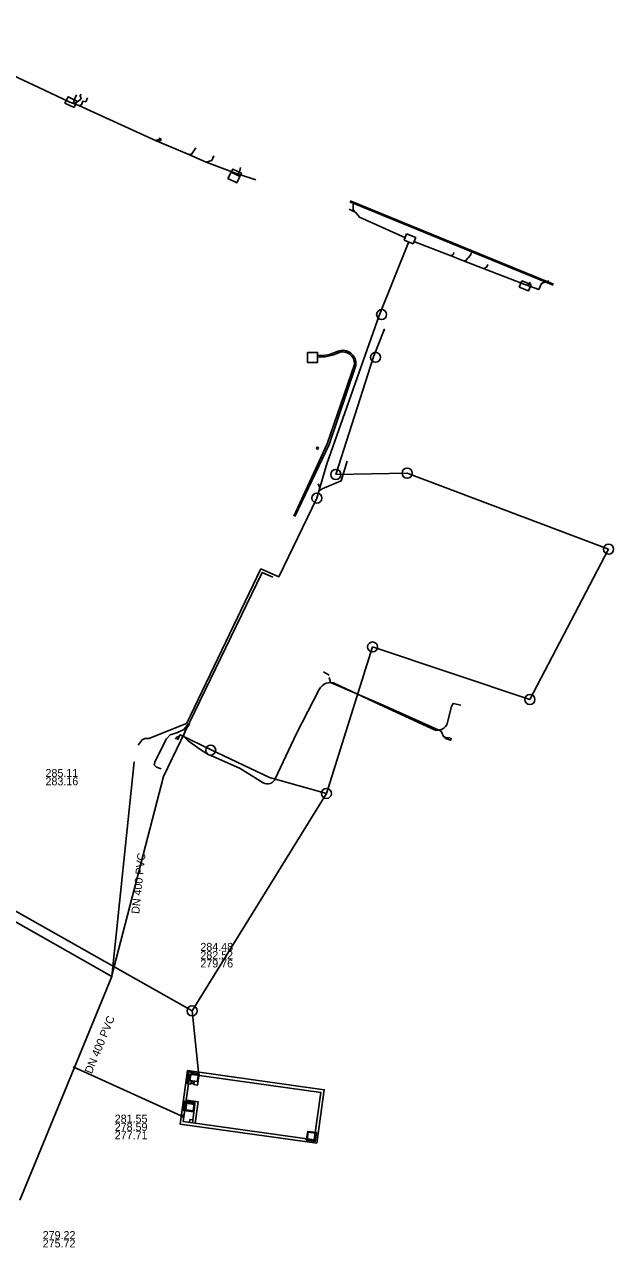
# Model space of a CAD drawing. Extents: x -600391 to -599491, y -1160176 to -1159402.
# Drawn here: x -599654.5 to -599595.6, y -1160008 to -1159885.7 of the extents above; entities that cross this region are included whole.
import ezdxf

# ---------------------------------------------------------------- set-up
doc = ezdxf.new("R2010")
doc.units = 0
for name, color, linetype in [('Vrstva 1', 7, 'Continuous'), ('Vrstva 12', 7, 'Continuous'), ('Vrstva 13', 7, 'Continuous'), ('Vrstva 15', 7, 'Continuous'), ('Vrstva 3', 7, 'Continuous'), ('Vrstva 5', 7, 'Continuous'), ('Vrstva 7', 7, 'Continuous'), ('Vrstva 9', 7, 'Continuous')]:
    doc.layers.add(name, color=color, linetype=linetype)

msp = doc.modelspace()

# ---------------------------------------------------------------- linework, layer by layer
at = {"layer": 'Vrstva 1'}
for p, q in [((-599619.58, -1159918.92), (-599623.36, -1159930.69)), ((-599623.36, -1159930.69), (-599616.23, -1159930.56)), ((-599616.23, -1159930.56), (-599596.1, -1159938.16)), ((-599596.1, -1159938.16), (-599603.96, -1159953.18)), ((-599663.77, -1159969.62), (-599637.73, -1159984.3))]:
    msp.add_line(p, q, dxfattribs=at)
for points in [[(-599618.52, -1159916.24), (-599619.58, -1159918.92)], [(-599629.64, -1159940.95), (-599630.72, -1159940.5), (-599638, -1159955.48)], [(-599619.69, -1159947.93), (-599624.3, -1159962.57)], [(-599603.96, -1159953.18), (-599619.69, -1159947.93)], [(-599638, -1159955.48), (-599640.59, -1159960.87)], [(-599639.38, -1159957.16), (-599639.26, -1159956.94), (-599639, -1159956.86)], [(-599635.89, -1159958.19), (-599638.93, -1159956.72), (-599639.18, -1159957.23)], [(-599635.89, -1159958.19), (-599629.99, -1159960.97), (-599624.3, -1159962.57)], [(-599640.59, -1159960.87), (-599645.75, -1159980.77)], [(-599624.3, -1159962.57), (-599637.73, -1159984.3)], [(-599637.73, -1159984.3), (-599637.05, -1159990.75)], [(-599638.81, -1159994.8), (-599649.61, -1159989.89)], [(-599625.25, -1159997.53), (-599624.52, -1159992.19), (-599638.18, -1159990.26), (-599638.92, -1159995.63), (-599625.25, -1159997.53)], [(-599625.54, -1159997.19), (-599624.85, -1159992.45), (-599637.94, -1159990.62), (-599638.61, -1159995.36), (-599625.54, -1159997.19)], [(-599637.85, -1159991.63), (-599637.82, -1159991.38), (-599637.51, -1159991.44), (-599637.54, -1159991.68), (-599637.2, -1159991.74), (-599637.03, -1159990.59), (-599638.07, -1159990.41), (-599638.23, -1159991.57), (-599637.85, -1159991.63)], [(-599637.96, -1159991.25), (-599637.83, -1159990.52), (-599637.1, -1159990.65), (-599637.23, -1159991.38), (-599637.96, -1159991.25)], [(-599637.84, -1159991.56), (-599637.81, -1159991.4), (-599637.51, -1159991.45), (-599637.54, -1159991.61), (-599637.84, -1159991.56)], [(-599637.44, -1159993.47), (-599638.47, -1159993.34), (-599638.6, -1159994.25), (-599637.54, -1159994.41), (-599637.44, -1159993.47)], [(-599638.35, -1159994.2), (-599638.26, -1159993.47), (-599637.53, -1159993.56), (-599637.62, -1159994.29), (-599638.35, -1159994.2)], [(-599637.7, -1159995.49), (-599637.46, -1159993.65), (-599638.35, -1159993.52)], [(-599638.29, -1159993.23), (-599637.12, -1159993.4), (-599637.41, -1159995.53)], [(-599638.82, -1159994.9), (-599638.52, -1159994.74)], [(-599638.79, -1159994.7), (-599638.52, -1159994.74)], [(-599638.55, -1159994.94), (-599638.79, -1159994.7)], [(-599638.82, -1159994.9), (-599638.55, -1159994.94)], [(-599638, -1159995.45), (-599637.96, -1159995.15)], [(-599637.96, -1159995.15), (-599637.66, -1159995.19)], [(-599625.29, -1159996.47), (-599625.42, -1159997.35), (-599626.31, -1159997.22), (-599626.17, -1159996.35), (-599625.29, -1159996.47)], [(-599626.21, -1159997.17), (-599626.12, -1159996.44), (-599625.39, -1159996.53), (-599625.48, -1159997.26), (-599626.21, -1159997.17)]]:
    msp.add_lwpolyline(points, dxfattribs=at)
at = {"layer": 'Vrstva 13'}
for points in [[(-599621.5, -1159919.7), (-599624.21, -1159927.64), (-599627.55, -1159934.85)], [(-599627.45, -1159934.89), (-599624.03, -1159927.68), (-599621.36, -1159919.79)], [(-599623.38, -1159951.61), (-599618.57, -1159953.87), (-599613.8, -1159956.07)], [(-599629.41, -1159961.1), (-599627.28, -1159956.59), (-599625.02, -1159952.19)], [(-599612.26, -1159955.71), (-599611.8, -1159953.87), (-599611.64, -1159953.59), (-599610.88, -1159953.74)], [(-599638.1, -1159955.6), (-599638.54, -1159956.18), (-599639.24, -1159956.53), (-599639.91, -1159956.73), (-599640.27, -1159957.13), (-599641.42, -1159959.34), (-599641.52, -1159959.71), (-599641.3, -1159959.95), (-599640.82, -1159960.13)], [(-599637.97, -1159955.65), (-599638.4, -1159956.17), (-599638.58, -1159956.84), (-599638.12, -1159957.3), (-599636.94, -1159958.15), (-599636.11, -1159958.67), (-599635.38, -1159958.99), (-599632.93, -1159960.09), (-599631.43, -1159961.01), (-599630.62, -1159961.52)]]:
    msp.add_lwpolyline(points, dxfattribs=at)
for centre, radius, start, end in [((-599624.91, -1159914.91), 4.04, 265.0043, 297.1026), ((-599624.91, -1159914.91), 3.88, 265.0043, 297.1037), ((-599622.66, -1159919.59), 1.31, 351.0162, 111.9016), ((-599622.66, -1159919.6), 1.16, 354.9209, 110.9386), ((-599623.91, -1159952.72), 1.23, 64.4628, 154.4903), ((-599613.2, -1159955.18), 1.08, 235.8449, 330.4702), ((-599630.21, -1159960.74), 0.881, 242.4813, 335.8033)]:
    msp.add_arc(centre, radius, start, end, dxfattribs=at)
at = {"layer": 'Vrstva 15'}
msp.add_lwpolyline([(-599626.19, -1159919.49), (-599625.19, -1159919.49), (-599625.19, -1159918.49), (-599626.19, -1159918.49)], close=True, dxfattribs=at)
msp.add_circle((-599625.2, -1159928.07), 0.1, dxfattribs=at)
at = {"layer": 'Vrstva 3'}
for centre in [(-599619.39, -1159918.98), (-599623.36, -1159930.69), (-599616.23, -1159930.56), (-599596.1, -1159938.16), (-599619.69, -1159947.93), (-599603.96, -1159953.18), (-599635.87, -1159958.24), (-599624.3, -1159962.57), (-599637.73, -1159984.3)]:
    msp.add_circle(centre, 0.5, dxfattribs=at)
at = {"layer": 'Vrstva 5'}
for p, q in [((-599649.61, -1159893.6), (-599649.4, -1159893.06)), ((-599633.19, -1159900.64), (-599631.36, -1159901.25)), ((-599621.5, -1159904.44), (-599621.63, -1159904.22)), ((-599616.54, -1159907.27), (-599616.28, -1159906.63)), ((-599615.36, -1159907.01), (-599615.63, -1159907.65)), ((-599605.03, -1159911.97), (-599604.77, -1159911.32)), ((-599604.03, -1159911.68), (-599603.95, -1159911.46))]:
    msp.add_line(p, q, dxfattribs=at)
for points in [[(-599649.96, -1159893.49), (-599653.06, -1159892.02), (-599662.35, -1159887.67), (-599663.43, -1159887.16), (-599663.78, -1159887), (-599666.58, -1159885.71)], [(-599649.52, -1159894.01), (-599650.44, -1159893.57), (-599650.13, -1159892.95), (-599649.24, -1159893.37), (-599649.52, -1159894.01)], [(-599648.91, -1159892.82), (-599648.91, -1159892.86), (-599648.81, -1159893.13), (-599648.88, -1159893.22), (-599649.23, -1159893.43), (-599649.25, -1159893.49), (-599649.46, -1159893.58)], [(-599649.4, -1159893.06), (-599649.28, -1159892.74)], [(-599648.91, -1159892.82), (-599648.83, -1159892.67)], [(-599648.35, -1159893.46), (-599648.19, -1159893.05)], [(-599649.96, -1159893.49), (-599649.77, -1159893.54), (-599649.05, -1159893.81), (-599641.37, -1159897.3)], [(-599649.05, -1159893.81), (-599648.79, -1159893.75), (-599648.64, -1159893.38), (-599648.35, -1159893.46)], [(-599641.37, -1159897.3), (-599641.02, -1159897.2), (-599640.95, -1159897.05)], [(-599636.33, -1159899.46), (-599638.04, -1159898.72), (-599641.37, -1159897.3)], [(-599641.07, -1159897.43), (-599640.79, -1159897.2)], [(-599640.85, -1159897.06), (-599640.87, -1159897.13), (-599640.84, -1159897.22)], [(-599640.84, -1159897.22), (-599640.79, -1159897.2)], [(-599637.34, -1159898.05), (-599637.74, -1159898.65), (-599638.04, -1159898.72)], [(-599635.76, -1159899.31), (-599636.33, -1159899.46)], [(-599635.76, -1159899.31), (-599635.55, -1159898.85)], [(-599633.38, -1159900.56), (-599636.33, -1159899.46)], [(-599633.83, -1159900.48), (-599632.95, -1159900.91), (-599633.25, -1159901.53), (-599634.14, -1159901.1), (-599633.83, -1159900.48)], [(-599633.83, -1159900.48), (-599633.67, -1159900.16), (-599632.79, -1159900.59), (-599632.95, -1159900.91)], [(-599633.01, -1159900.57), (-599633.19, -1159900.64), (-599633.38, -1159900.56)], [(-599633.01, -1159900.57), (-599632.88, -1159900)], [(-599621.4, -1159904.46), (-599621.5, -1159904.44), (-599622.04, -1159904.17)], [(-599601.65, -1159911.77), (-599621.96, -1159903.45)], [(-599601.6, -1159911.66), (-599621.91, -1159903.33)], [(-599621.63, -1159904.22), (-599621.63, -1159903.79), (-599621.63, -1159903.66)], [(-599616.39, -1159907.04), (-599621.01, -1159904.98), (-599621.4, -1159904.46)], [(-599616.28, -1159906.63), (-599615.36, -1159907.01)], [(-599616.1, -1159907.51), (-599619.04, -1159914.79)], [(-599616.54, -1159907.27), (-599615.63, -1159907.65)], [(-599615.55, -1159907.39), (-599611.94, -1159908.8), (-599610.59, -1159909.32), (-599604.47, -1159911.71), (-599603.07, -1159912.21), (-599602.8, -1159911.59), (-599602.26, -1159911.41), (-599602.08, -1159911.32)], [(-599611.58, -1159908.49), (-599611.59, -1159908.67), (-599611.77, -1159908.82), (-599611.94, -1159908.8)], [(-599609.83, -1159908.55), (-599609.88, -1159908.7), (-599609.93, -1159908.81), (-599610.36, -1159909.3), (-599610.59, -1159909.32)], [(-599608.49, -1159910.07), (-599608.27, -1159909.95), (-599608.18, -1159909.71)], [(-599604.77, -1159911.32), (-599603.85, -1159911.7)], [(-599603.85, -1159911.7), (-599604.11, -1159912.34), (-599605.03, -1159911.97)], [(-599604.27, -1159911.78), (-599604.24, -1159911.77), (-599604.03, -1159911.68)], [(-599624.25, -1159929.63), (-599619.04, -1159914.79)], [(-599625.25, -1159933.05), (-599624.25, -1159929.63)], [(-599622.21, -1159929.36), (-599622.82, -1159931.33), (-599624.71, -1159932.14), (-599625.03, -1159932.31)], [(-599624.95, -1159932.01), (-599625.13, -1159931.62)], [(-599625.25, -1159933.05), (-599629.06, -1159940.93), (-599630.84, -1159940.13), (-599637.88, -1159954.78)], [(-599624.02, -1159950.76), (-599624.6, -1159950.43)], [(-599624.02, -1159950.97), (-599623.89, -1159951.48), (-599618.62, -1159953.76), (-599612.82, -1159956.36), (-599612.59, -1159956.89), (-599612.47, -1159956.95), (-599612.39, -1159957.08), (-599611.91, -1159957.25), (-599611.82, -1159957.02)], [(-599638.27, -1159955.58), (-599642.06, -1159957.07), (-599642.33, -1159957.09), (-599642.44, -1159957.08), (-599642.73, -1159957.22), (-599643.13, -1159957.76)], [(-599637.88, -1159954.78), (-599638.27, -1159955.58)], [(-599612.47, -1159956.95), (-599612.04, -1159957.04), (-599612.02, -1159956.95)]]:
    msp.add_lwpolyline(points, dxfattribs=at)
at = {"layer": 'Vrstva 7'}
for centre, radius in [((-599618.78, -1159914.71), 0.5), ((-599618.52, -1159916.24), 0.05), ((-599625.25, -1159933.05), 0.5)]:
    msp.add_circle(centre, radius, dxfattribs=at)
at = {"layer": 'Vrstva 9'}
for p, q in [((-599690.16, -1159955.66), (-599645.76, -1159980.86)), ((-599643.52, -1159959.41), (-599645.76, -1159980.86)), ((-599645.76, -1159980.86), (-599649.52, -1159990.03)), ((-599649.52, -1159990.03), (-599654.93, -1160003.22))]:
    msp.add_line(p, q, dxfattribs=at)

# ---------------------------------------------------------------- texts
at = {"layer": 'Vrstva 12'}
for s, p in [('285.11', (-599652.38, -1159960.93)), ('283.16', (-599652.38, -1159961.76)), ('284.48', (-599636.9, -1159978.31)), ('282.52', (-599636.9, -1159979.14)), ('279.76', (-599636.9, -1159979.97)), ('281.55', (-599645.46, -1159995.48)), ('278.59', (-599645.46, -1159996.31)), ('277.71', (-599645.46, -1159997.14)), ('279.22', (-599652.66, -1160007.12)), ('275.72', (-599652.66, -1160007.95))]:
    msp.add_text(s, height=0.8, dxfattribs=at).set_placement(p)
for rotation, p in [(84.0529, (-599643.01, -1159974.64)), (67.6663, (-599647.76, -1159990.66))]:
    msp.add_text('DN 400 PVC', height=0.8, rotation=rotation, dxfattribs=at).set_placement(p)

doc.saveas('drawing.dxf')
